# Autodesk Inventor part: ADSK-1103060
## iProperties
Shininess: 50.0
Length Units: 11272
Angle Units: 11279
Time Units: 11290
Mass Units: 11286
Length Display Precision: 4
Angle Display Precision: 2
Compacted: True
Created: 2000-09
Part Number: ADSK-1103060
Document SubType Name: Modeling
Description: HIGH SPEED NEEDLE
Mass: 1.42923 g
Surface Area: 4.98892 cm^2
Volume: 0.52739 cm^3
Density: 2.71 g/cm^3
Material: Aluminum-6061
Density: 0.0
Volumn: 0.0
Area: 0.0
PropertySet Name: Model Information
Control State: 0
Master: False
Checked Out: False
Author: Autodesk, Inc.
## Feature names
1. Extrusion4
